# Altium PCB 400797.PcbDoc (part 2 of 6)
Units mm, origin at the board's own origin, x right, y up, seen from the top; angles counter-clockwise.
Board outline 155 x 63.5 mm, 4 copper layers (Top Layer, Mid-Layer 1, Mid-Layer 2, Bottom Layer), stack 1.514 mm thick; 317 components, 286 nets, 1519 pads, 2174 vias.
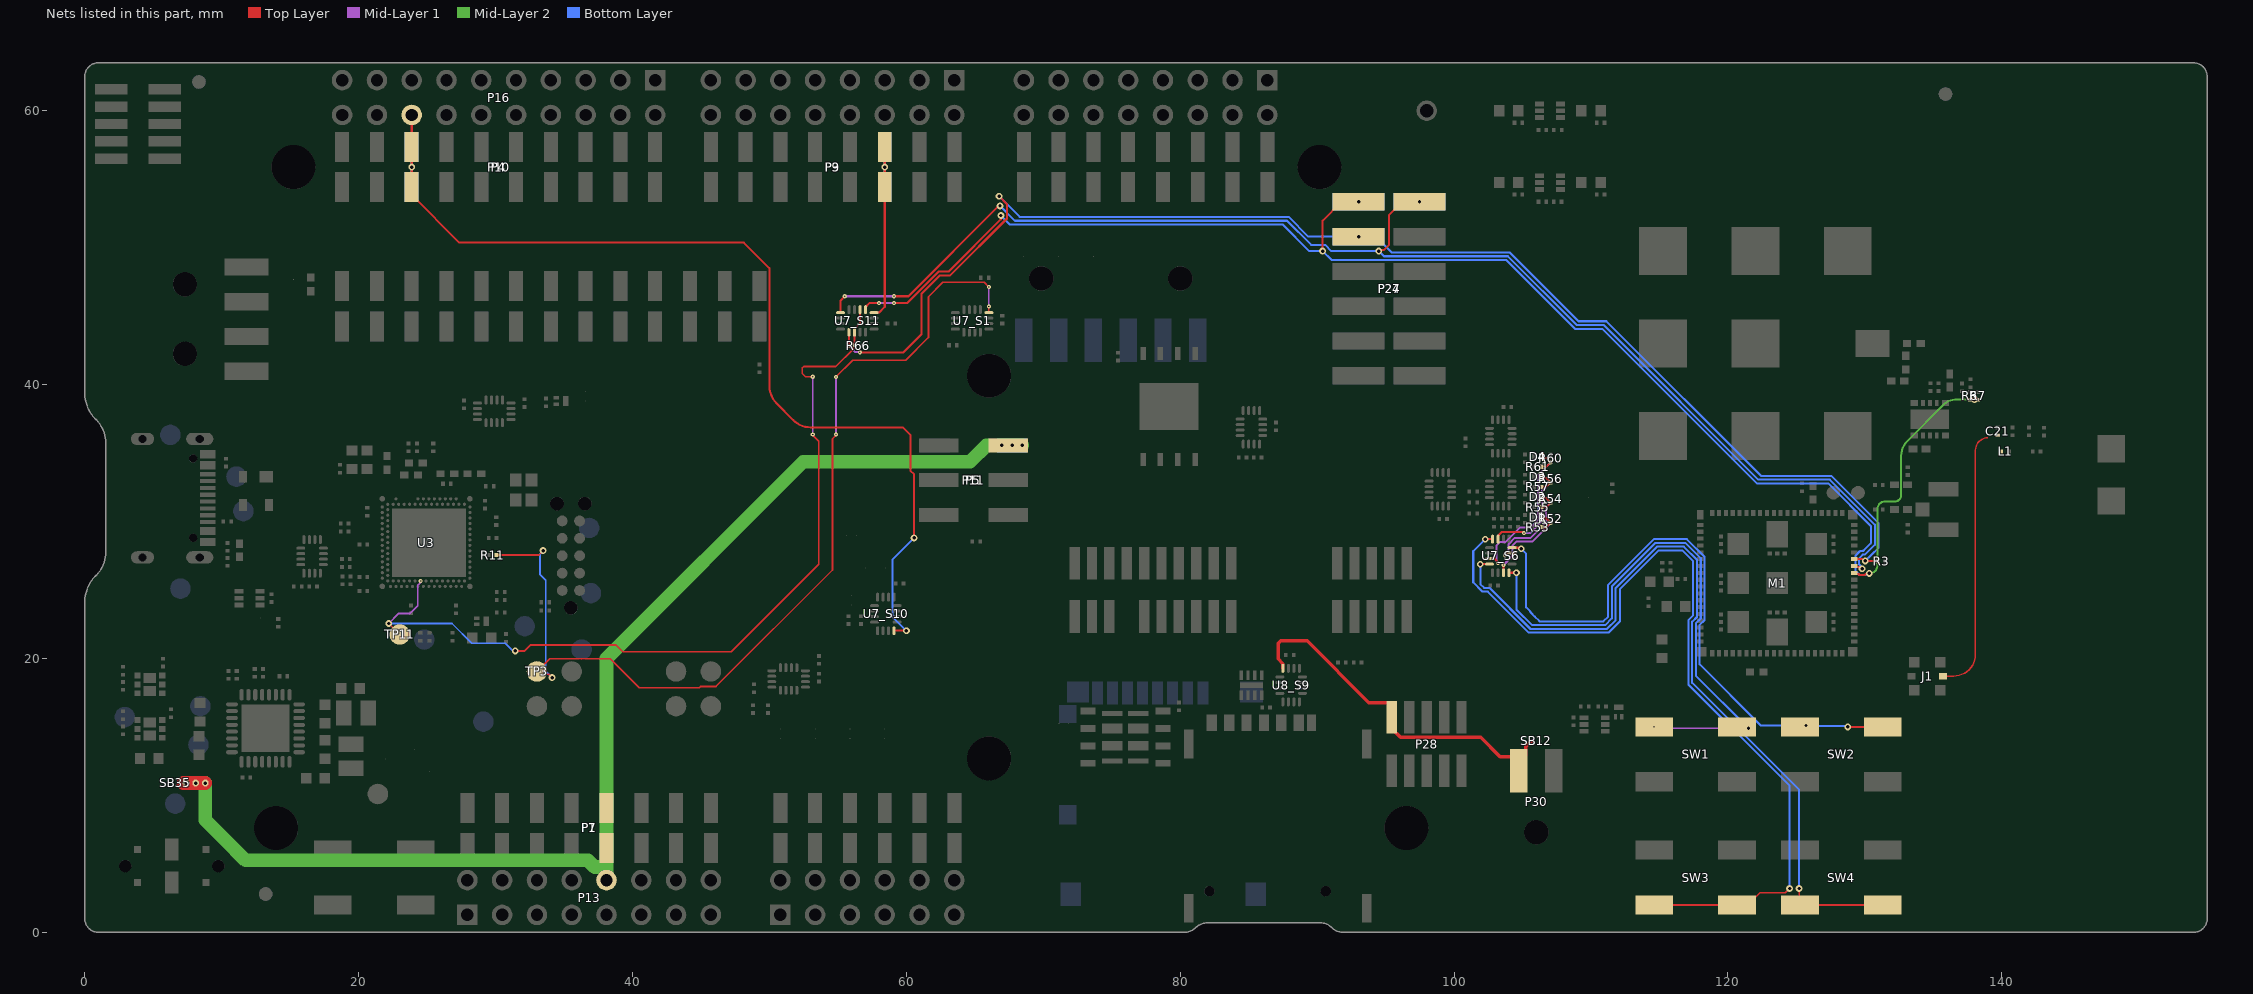
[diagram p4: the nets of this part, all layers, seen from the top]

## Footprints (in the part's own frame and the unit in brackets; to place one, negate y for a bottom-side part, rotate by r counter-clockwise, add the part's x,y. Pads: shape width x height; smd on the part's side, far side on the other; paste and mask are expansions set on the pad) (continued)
P822601 [mm] "Molded Diode, 2-Leads, Body 22,00x7,00mm, IPC Medium Density"
  rect 2x2 smd: 1(-8.89,-2.286) 2(-5.08,-2.286)
  Top Layer region: -21.6,1.254 -24.5,1.254 -24.5,3.754 -21.6,3.754
  Top Layer region: -22.4,-0.846 -24.5,-0.846 -24.5,0.854 -22.4,0.854
  Top Layer region: -21.6,-3.746 -24.5,-3.746 -24.5,-1.246 -21.6,-1.246
  Top Layer region: 24.6,-5.796 12.05,-5.796 12.05,-2.046 24.6,-2.046
  Top Layer region: 24.6,-2.046 21.7,-2.046 21.7,3.754 24.6,3.754
  Top Layer region: -3.67,-7.991 -8.05,-7.991 -8.05,-5.996 -3.67,-5.996
  Top Layer region: -3.67,-5.996 -5.71,-5.996 -5.71,-3.826 -3.67,-3.826
  Top Layer region: -3.67,-3.826 -6.399,-3.826 -6.4,-0.566 -3.67,-0.566
  Top Layer region: -10.45,-7.996 -12.45,-7.996 -12.45,-6.496 -10.45,-6.496
  Top Layer region: -9.2,-6.496 -12.45,-6.496 -12.45,-5.996 -9.2,-5.996
  Top Layer region: -9.45,-7.496 -9.95,-7.496 -9.95,-7.296 -9.45,-7.296
  Top Layer region: -8.45,-7.496 -8.95,-7.496 -8.95,-7.296 -8.45,-7.296
  Top Layer region: -8.45,-7.296 -9.95,-7.296 -9.95,-7.096 -8.45,-7.096
  Top Layer region: -9.45,-7.096 -9.95,-7.096 -9.95,-6.896 -9.45,-6.896
  Top Layer region: -8.45,-7.096 -8.95,-7.096 -8.95,-6.896 -8.45,-6.896
  Top Layer region: -8.6,-6.896 -8.8,-6.896 -8.8,-5.696 -8.6,-5.696
  Top Layer region: -8.2,-5.696 -9.2,-5.696 -9.2,-3.796 -8.2,-3.796
  Top Layer region: -7.3,-3.796 -10.4,-3.796 -10.4,-0.596 -7.3,-0.596
  Top Layer region: -9.45,-9.796 -9.95,-9.796 -9.95,-9.596 -9.45,-9.596
  Top Layer region: -8.45,-9.796 -8.95,-9.796 -8.95,-9.596 -8.45,-9.596
  Top Layer region: -8.45,-9.596 -9.95,-9.596 -9.95,-9.396 -8.45,-9.396
  Top Layer region: -9.45,-9.396 -9.95,-9.396 -9.95,-9.196 -9.45,-9.196
  Top Layer region: -8.45,-9.396 -8.95,-9.396 -8.95,-9.196 -8.45,-9.196
  Top Layer region: -9.6,-9.196 -9.8,-9.196 -9.8,-8.596 -9.6,-8.596
  Top Layer region: -9.45,-8.596 -9.95,-8.596 -9.95,-8.396 -9.45,-8.396
  Top Layer region: -8.45,-8.596 -8.95,-8.596 -8.95,-8.396 -8.45,-8.396
  Top Layer region: -8.45,-8.396 -9.95,-8.396 -9.95,-8.196 -8.45,-8.196
  Top Layer region: -9.45,-8.196 -9.95,-8.196 -9.95,-7.996 -9.45,-7.996
  Top Layer region: -8.45,-8.196 -8.95,-8.196 -8.95,-7.996 -8.45,-7.996
  Top Layer region: -9.6,-11.296 -9.8,-11.296 -9.8,-10.896 -9.6,-10.896
  Top Layer region: -9.45,-10.896 -9.95,-10.896 -9.95,-10.696 -9.45,-10.696
  Top Layer region: -8.45,-10.896 -8.95,-10.896 -8.95,-10.696 -8.45,-10.696
  Top Layer region: -8.45,-10.696 -9.95,-10.696 -9.95,-10.496 -8.45,-10.496
  Top Layer region: -9.45,-10.496 -9.95,-10.496 -9.95,-10.296 -9.45,-10.296
  Top Layer region: -8.45,-10.496 -8.95,-10.496 -8.95,-10.296 -8.45,-10.296
  Top Layer region: 24.75,-11.296 -8.05,-11.296 -8.05,-8.001 24.75,-8.001
  Top Layer region: -10.45,-11.296 -24.65,-11.296 -24.65,-7.996 -10.45,-7.996
  Bottom Layer region: -22.5,-3.546 -24.5,-3.546 -24.5,-2.546 -22.5,-2.546
  Bottom Layer region: -24.196,-2.546 -24.5,-2.546 -24.5,-2.046 -24.196,-2.046
  Bottom Layer region: -22.5,-2.046 -24.5,-2.046 -24.5,-1.046 -22.5,-1.046
  Bottom Layer region: -22.5,-1.046 -22.8,-1.046 -22.8,-0.546 -22.5,-0.546
  Bottom Layer region: -22.5,-0.546 -24.5,-0.546 -24.5,3.754 -22.5,3.754
  Bottom Layer region: -21,-3.546 -22,-3.546 -22,-1.046 -21,-1.046
  Bottom Layer region: -22.5,-5.046 -24.5,-5.046 -24.5,-4.046 -22.5,-4.046
  Bottom Layer region: 7.7,-5.796 6.7,-5.796 6.7,-4.896 7.7,-4.896
  Bottom Layer region: 9.2,-5.796 8.2,-5.796 8.2,-4.896 9.2,-4.896
  Bottom Layer region: 10.7,-5.796 9.7,-5.796 9.7,-4.896 10.7,-4.896
  Bottom Layer region: 13.2,-5.796 11.2,-5.796 11.2,-4.896 13.2,-4.896
  Bottom Layer region: 13.2,-4.896 6.7,-4.896 6.7,-4.596 13.2,-4.596
  Bottom Layer region: 7.7,-4.596 6.7,-4.596 6.7,-3.746 7.7,-3.746
  Bottom Layer region: 9.2,-4.596 8.2,-4.596 8.2,-3.746 9.2,-3.746
  Bottom Layer region: 10.7,-4.596 9.7,-4.596 9.7,-3.746 10.7,-3.746
  Bottom Layer region: 13.2,-4.596 11.2,-4.596 11.2,-3.746 13.2,-3.746
  Bottom Layer region: 6.2,-5.796 5.2,-5.796 5.2,-3.746 6.2,-3.746
  Bottom Layer region: 4.7,-5.796 3.7,-5.796 3.7,-3.746 4.7,-3.746
  Bottom Layer region: -3.86,-7.996 -12.45,-7.996 -12.45,-5.996 -3.86,-5.996
  Bottom Layer region: 24.752,-11.296 -24.648,-11.296 -24.65,-7.996 24.75,-7.996
  Multi-Layer pour cut-out: -39.95,5.08 39.05,5.08 39.05,-7.996 -39.95,-7.996
  silkscreen extent -25.2,-4.25 25.3,4.05, body extent -24.95,-4 25.05,4, height 3.2
RESC0603X03L_C [mm] "Chip Resistor, 2-Leads, Body 0.6x0.3mm, IPC High Density"
  rect 0.27x0.3 smd: 1(-0.285,0) 2(0.285,0)
  body extent -0.3,-0.15 0.3,0.15, height 0.23
RESC0603X03L_C_NC [mm] "Chip Resistor, 2-Leads, Body 0.6x0.3mm, IPC High Density"
  rect 0.27x0.3 smd: 1(-0.285,0) 2(0.285,0)
RESC1005X04L [mm] "Chip Resistor, 2-Leads, Body 1.0x0.5mm, IPC High Density"
  rect 0.6x0.55 smd mask+0.05: 1(-0.5,0) 2(0.5,0)
  body extent -0.5,-0.25 0.5,0.25, height 0.3
RESC1005X04L_NC [mm] "Chip Resistor, 2-Leads, Body 1.0x0.5mm, IPC High Density"
  rect 0.6x0.55 smd mask+0.05: 1(-0.5,0) 2(0.5,0)
SD-80259-001 [mm] "USB TYPE C RECEPTACLE, 16 PIN"
  round 0.6 hole 0.6 unplated: 0(-2.89,1.315) 0(2.89,1.315)
  oval 0.9x2 hole 0.6 slot 1.7 at 90 deg: 13(-4.325,1.795) 13(4.325,1.795)
  oval 0.9x1.7 hole 0.6 slot 1.4 at 90 deg: 13(-4.325,-2.385) 13(4.325,-2.385)
  rect 0.6x1.14 smd: A1(-3.2,2.385) A4(-2.4,2.385) A9(2.4,2.385) A12(3.2,2.385)
  rect 0.3x1.14 smd: A5(-1.25,2.385) A6(-0.25,2.385) A7(0.25,2.385) A8(1.25,2.385) B5(1.75,2.385) B6(0.75,2.385) B7(-0.75,2.385) B8(-1.75,2.385)
  oval 0.9x2 on Top Paste: ""(-4.32,1.795) ""(4.32,1.795)
  oval 0.9x1.7 on Top Paste: ""(-4.32,-2.385) ""(4.32,-2.385)
  silkscreen extent -4.33,-4.48 4.33,0.47, body extent -4.48,-4.98 4.48,2.74, height 3.26
SEGGER_LOGO_S [mm] "Logo 7.82 mm x 3.84 mm, print overlay"
  silkscreen extent -3.91,-1.92 3.91,1.92
Shunt_2.54mm_Horizontal [mm]
  body extent 0,-2.54 5.03,2.54, height 2.99
SKY65943-11 [mm]
  rect 0.425x0.515 smd mask+0.05: 1(-1.188,1.144) 5(-1.188,-1.144) 6(1.188,-1.144) 10(1.188,1.144)
  rect 0.425x0.275 smd mask+0.05: 2(-1.188,0.5) 3(-1.188,0) 4(-1.188,-0.5) 7(1.188,-0.5) 8(1.188,0) 9(1.188,0.5)
  rect 1.45x2.802 smd paste-2 mask-5: 11(0,0)
  rect 1.55x2.487 on Top Solder: ""(0,0)
  Top Layer region: -0.988,0.887 -0.713,0.887 -0.713,1.4 -0.988,1.4
  Top Layer region: 0.713,-1.4 0.988,-1.4 0.988,-0.887 0.713,-0.887
  Top Layer region: 0.712,0.362 0.987,0.362 0.987,0.637 0.712,0.637
  Top Layer region: -0.712,-0.362 -0.987,-0.362 -0.987,-0.637 -0.712,-0.637
  body extent -1.25,-1.25 1.25,1.25, height 0.71
SOCKET_1x6_SMD [mm] "Socket, 2.54mm, SMD"
  rect 1.02x2.19 smd: 1(0,-1.465) 1(0,1.465) 2(2.54,-1.465) 2(2.54,1.465) 3(5.08,-1.465) 3(5.08,1.465) 4(7.62,-1.465) 4(7.62,1.465) 5(10.16,-1.465) 5(10.16,1.465) 6(12.7,1.465) 6(12.7,-1.465)
  silkscreen extent -1.27,-1.27 13.97,1.27, body extent -1.27,-2.29 13.97,2.29, height 7.47
SOCKET_1x8_SMD [mm] "Socket, 2.54mm, SMD"
  rect 1.02x2.19 smd: 1(0,-1.465) 1(0,1.465) 2(2.54,-1.465) 2(2.54,1.465) 3(5.08,-1.465) 3(5.08,1.465) 4(7.62,-1.465) 4(7.62,1.465) 5(10.16,-1.465) 5(10.16,1.465) 6(12.7,1.465) 6(12.7,-1.465) 7(15.24,-1.465) 7(15.24,1.465) 8(17.78,-1.465) 8(17.78,1.465)
  silkscreen extent -1.27,-1.27 19.05,1.27, body extent -1.27,-2.29 19.05,2.29, height 7.47
SOCKET_1x10_SMD [mm] "Socket, 2.54mm, SMD"
  rect 1.02x2.19 smd: 1(0,1.465) 1(0,-1.465) 2(2.54,-1.465) 2(2.54,1.465) 3(5.08,-1.465) 3(5.08,1.465) 4(7.62,-1.465) 4(7.62,1.465) 5(10.16,-1.465) 5(10.16,1.465) 6(12.7,-1.465) 6(12.7,1.465) 7(15.24,-1.465) 7(15.24,1.465) 8(17.78,-1.465) 8(17.78,1.465) 9(20.32,-1.465) 9(20.32,1.465) 10(22.86,-1.465) 10(22.86,1.465)
  silkscreen extent -1.27,-1.27 24.13,1.27, body extent -1.27,-2.29 24.13,2.29, height 7.47
SOCKET_2x3_SMD-2.54mm-bottom-NC [mm] "Socket, 2.54mm, SMD"
  rect 1.02x2.22 smd far side: 1(-2.54,-2.825) 2(-2.54,2.825) 3(0,-2.825) 4(0,2.825) 5(2.54,-2.825) 6(2.54,2.825)
SOCKET_2x6_SMD-2.54mm#1 [mil]
  rect 50x150 smd: 1(-250,-87.5) 2(-250,87.5) 3(-150,-87.5) 4(-150,87.5) 5(-50,-87.5) 6(-50,87.5) 7(50,-87.5) 8(50,87.5) 9(150,-87.5) 10(150,87.5) 11(250,-87.5) 12(250,87.5)
  silkscreen extent -310,-127 300,100, body extent -300,-138 300,139, height 290
SOCKET_2x6_SMD-2.54mm#2 [mil] "Board-Board Conn, Header, 4-way, 2-row"
  rect 50x150 smd: 1(-250,87.5) 2(-250,-87.5) 3(-150,87.5) 4(-150,-87.5) 5(-50,87.5) 6(-50,-87.5) 7(50,87.5) 8(50,-87.5) 9(150,87.5) 10(150,-87.5) 11(250,87.5) 12(250,-87.5)
  silkscreen extent -310,-100 300,127
SODFL35X40-2N [mm] "SODFL, 2-Leads, Body 0,60x0,35mm, IPC Medium Density"
  rect 0.25x0.6 smd: 1(-0.325,0) 3(0.325,0)
  body extent -0.53,-0.33 0.53,0.33, height 0.4
Solderbridge [mil]
  round 1 smd paste-99999: 1(-13.78,0) 2(13.78,0)
  Top Layer region: -7.49,19.36 -15.76,15.74 -21.55,8.8 -23.62,0 -23.62,0 -21.55,-8.79 -15.76,-15.74 -7.49,-19.36 -7.49,-19.36 -6.18,-19.31 -5.02,-18.71 -4.22,-17.68 -3.94,-16.4 -3.94,-16.4 -3.94,16.4 -4.22,17.68 -5.02,18.71 -6.18,19.31 -7.49,19.36
  Top Layer region: 7.49,-19.36 15.76,-15.74 21.55,-8.8 23.62,0 23.62,0 21.55,8.79 15.76,15.74 7.49,19.36 7.49,19.36 6.18,19.31 5.02,18.71 4.22,17.68 3.94,16.4 3.94,16.4 3.94,-16.4 4.22,-17.68 5.02,-18.71 6.18,-19.31 7.49,-19.36
Solderbridge_Shorted [mil]
  round 1 smd paste-99999: 1(-13.78,0) 2(13.78,0)
  Top Layer region: -4.92,3.94 -4.92,-3.94 4.92,-3.94 4.92,3.94
  Top Layer region: -7.49,19.36 -15.76,15.74 -21.55,8.8 -23.62,0 -23.62,0 -21.55,-8.79 -15.76,-15.74 -7.49,-19.36 -7.49,-19.36 -6.18,-19.31 -5.02,-18.71 -4.22,-17.68 -3.94,-16.4 -3.94,-16.4 -3.94,16.4 -4.22,17.68 -5.02,18.71 -6.18,19.31 -7.49,19.36
  Top Layer region: 7.49,-19.36 15.76,-15.74 21.55,-8.8 23.62,0 23.62,0 21.55,8.79 15.76,15.74 7.49,19.36 7.49,19.36 6.18,19.31 5.02,18.71 4.22,17.68 3.94,16.4 3.94,16.4 3.94,-16.4 4.22,-17.68 5.02,-18.71 6.18,-19.31 7.49,-19.36
Solderbridge_Shorted_Power [mil]
  round 1 smd paste-99999: 1(-13.84,0.21) 2(13.72,0.21)
  Top Layer region: -4.92,9.84 4.92,9.84 4.92,-9.84 -4.92,-9.84
  Top Layer region: 7.43,-19.16 15.71,-15.53 21.49,-8.59 23.56,0.21 23.56,0.21 21.49,9 15.71,15.94 7.43,19.57 7.43,19.57 6.12,19.52 4.96,18.92 4.16,17.89 3.88,16.61 3.88,16.61 3.88,-16.2 4.16,-17.47 4.96,-18.51 6.12,-19.11 7.43,-19.16
  Top Layer region: -7.54,19.57 -15.82,15.94 -21.61,9 -23.68,0.21 -23.68,0.21 -21.61,-8.59 -15.82,-15.53 -7.54,-19.16 -7.54,-19.16 -6.24,-19.11 -5.08,-18.51 -4.28,-17.47 -4,-16.2 -3.99,-16.2 -3.99,16.61 -4.28,17.89 -5.08,18.92 -6.24,19.52 -7.54,19.57
SON50P210X160X65_HS-9N [mm] "SON, 8-Leads, Body 2.10x1.60mm, Pitch 0.50mm, Thermal Pad 1.70x0.4mm, IPC Medium Density"
  rect 0.7x0.25 smd mask+0.05: 1(-0.725,0.75) 2(-0.725,0.25) 3(-0.725,-0.25) 4(-0.725,-0.75) 5(0.725,-0.75) 6(0.725,-0.25) 7(0.725,0.25) 8(0.725,0.75)
  rect 0.4x1.7 smd paste-2 mask+0.05: 9(0,0)
  rect 0.3x0.75 on Top Paste: ""(0,0.425) ""(0,-0.425)
  silkscreen extent -1.26,1.2 -1.16,1.26, body extent -0.85,-1.1 0.85,1.1, height 0.65
SON127P600X90_HS-8N [mm] "SON, 8-Leads, Body 5.00x6.00mm, Pitch 1.27mm, IPC Medium Density"
  rect 1.5x0.35 smd paste-1.27: 0(-0.95,-1.73) 0(-0.95,1.73) 0(0.95,-1.73) 0(0.95,1.73)
  rect 1.5x0.7 smd paste-1.27: 0(-0.95,-0.635) 0(-0.95,0.635) 0(0.95,-0.635) 0(0.95,0.635)
  rect 1.1x0.5 smd paste-1.27: 1(-2.75,1.905) 2(-2.75,0.635) 3(-2.75,-0.635) 4(-2.75,-1.905) 5(2.75,-1.905) 6(2.75,-0.635) 7(2.75,0.635) 8(2.75,1.905)
  silkscreen extent -3.6,-2.58 3.08,2.72, body extent -3,-2.5 3,2.5, height 0.65
SON127P800X80_HS-9N [mm] "SON, 8-Leads, Body 6.00x8.00mm, Pitch 1.27mm, Thermal Pad 4.30x3.40mm, IPC Medium Density"
  rect 0.95x0.4 smd: 1(-3.87,1.905) 2(-3.87,0.635) 3(-3.87,-0.635) 4(-3.87,-1.905) 5(3.87,-1.905) 6(3.87,-0.635) 7(3.87,0.635) 8(3.87,1.905)
  rect 3.4x4.3 smd paste-1.7: 9(0,0)
  silkscreen extent -4.52,-3.18 4.18,3.52, body extent -4.05,-3.05 4.05,3.05, height 0.8
SOT190P230X110-4L [mm] "SOT143, 4-Leads, Body 3.0x2.5mm (max), Pitch 1.90mm, IPC High Density"
  rect 0.85x1 smd: 1(-1.025,0.75)
  rect 0.85x0.6 smd: 2(-1.025,-0.95) 3(1.025,-0.95) 4(1.025,0.95)
  silkscreen extent -1.15,-1.5 0.25,1.93, body extent -1.21,-1.46 1.21,1.46, height 1
SOTFL50P162X60-6N [mm] "SOTFL, 6-Leads, Body 1.60x1.63mm, Pitch 0.50mm, IPC Medium Density"
  rect 0.65x0.35 smd: 1(-0.775,0.5) 2(-0.775,0) 3(-0.775,-0.5) 4(0.775,-0.5) 5(0.775,0) 6(0.775,0.5)
  silkscreen extent -0.9,-0.82 0.05,1.35, body extent -0.81,-0.85 0.81,0.85, height 0.6
TC2050-IDC-NLFP [mil]
  round 39 hole 39 unplated: 0(-150,0) 0(150,-40) 0(150,40)
  round 31 smd paste-196.85: 1(-100,-25) 2(-50,-25) 3(0,-25) 4(50,-25) 5(100,-25) 6(100,25) 7(50,25) 8(0,25) 9(-50,25) 10(-100,25)
  Top Layer pour cut-out: -100,25 -100,-25 100,-25 100,25
TESTPAD-TH [mm]
  round 1.5 hole 1: 1(0,0)
TP_SMD_D1.0mm [mm] "Test point - pad 1.0mm"
  round 1 smd paste-5: 1(0,0)
TP_SMD_D1.5mm [mm] "Test point - pad 1.5mm"
  round 1.5 smd paste-5: 1(0,0)
  body extent -0.75,-0.75 0.75,0.75, height 0.05
WEE_3x4.5mm [mm]
  silkscreen extent -1.47,-2.7 1.47,1.71
XQFN40P180X260X50-16N [mm] "QFN, 16-Leads, Body 1.80x2.60mm, Pitch 0.40mm, IPC Medium Density"
  oval 0.65x0.22 smd paste-0.02 mask+0.04: 1(-0.825,0.6) 2(-0.825,0.2) 3(-0.825,-0.2) 4(-0.825,-0.6) 9(0.825,-0.6) 10(0.825,-0.2) 11(0.825,0.2) 12(0.825,0.6)
  oval 0.22x0.65 smd paste-0.02 mask+0.04: 5(-0.6,-1.225) 6(-0.2,-1.225) 7(0.2,-1.225) 8(0.6,-1.225) 13(0.6,1.225) 14(0.2,1.225) 15(-0.2,1.225) 16(-0.6,1.225)
  body extent -0.91,-1.31 0.91,1.31, height 0.55

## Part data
A1: "ANTENNA PRESTTA OCTABAND LTE", Manufacturer=Ethertronics, Part number IPS=00000009001, Part number NEMS=100700043, Part number Norautron=N.A.
A2: library part DSGP.1575.18.4.C.02, "18 x 18 mm Low Profile GPS L1 / GALILEO E1 Passive Patch Antenna", Manufacturer=Taoglas, Part number IPS=00000007687, Part number NEMS=100700073, Part number Norautron=N.A.
C1 C2: library part C0201-1Âµ0-10V-X5R-GRM033R61A105ME15, "Capacitor, X5R, Â±20%, 10V", Manufacturer=Murata, Manufacturer Part Number=GRM033R61A105ME15, Part number IPS=N.A., Part number NEMS=100200545, Supplier Part Number 1=490-13226-1-ND
C3 C7: library part C0603-10Âµ-10V-X6S-GRM188C81A106MA73, "Capacitor, Ceramic, 10ÂµF 10V X6S 0603,Â±20%", Manufacturer=Murata, Manufacturer Part Number=GRM188C81A106MA73, Part number IPS=N.A., Part number NEMS=100200520, Supplier Part Number 1=490-7197-2-ND
C4 C10 C15 C16 C24 C25 C26 C27 C31 C32 C33 C34 C39 C42 C43 C51 C52_S1 C52_S2 C52_S3 C52_S4 C52_S5 C52_S6 C52_S8 C52_S10 C52_S11 C53_S7 C53_S9 C62: library part C0201-100n, "Capacitor, X5R, Â±10%", Manufacturer=N.A., Part number IPS="00000001248, 00000002505", Part number NEMS=100200078, Part number Norautron=262071862
C5 C6: library part C0402-4Âµ7-10V-X5R, "Capacitor, X5R, 10V", Manufacturer=Murata, Manufacturer Part Number=GRM155R61A475MEAAD, Part number IPS=N.A., Part number NEMS=100200415, Supplier Part Number 1=490-14306-1-ND
C11 C12 C13: library part C0201-39p, "Capacitor, NP0, Â±1%, 25V", Manufacturer=Murata, Manufacturer Part Number=GRM0335C1E390FA01, Part number IPS=00000001668, Part number NEMS=100200039, Part number Norautron=N.A.
C14 C17: library part C0201-100p, "Capacitor, NP0, Â±2%, 25V", Manufacturer=Murata, Manufacturer Part Number=GRM0335C1E101GA01, Part number IPS=00000007853, Part number NEMS=100200044, Part number Norautron=N.A.
C18: library part C0402-N.C., "Not mounted", Manufacturer=N.A., Part number NEMS=100200105
C19 C21 C22 C23 C49: library part C0201-N.C., "Not mounted", Manufacturer=N.A., Part number NEMS=100200001
C20: library part C0201-3.5p, "Capacitor, NP0, Â±0.1pF, 25V", Manufacturer=Murata, Manufacturer Part Number=GJM0335C1H3R5BB01E, Part number IPS=00000001469, Part number NEMS=100200023, Part number Norautron=N.A.
C28 C29 C35 C36 C40: library part C0402-1Âµ0-10V-X5R, "Capacitor, Ceramic, X5R, Â±10%, 10V", Manufacturer=N.A., Part number NEMS=100200482
C30: library part C0201-2n2, "Capacitor, X7R, Â±10%, 10V", Manufacturer=N.A., Part number IPS=00000001778, Part number NEMS=100200060, Part number Norautron=26470002
C37 C38 C58: library part C0603-4Âµ7-10V-X5R, "Capacitor, Ceramic, X5R, Â±10%, 10V", Manufacturer=N.A., Part number NEMS=100200479, Part number Norautron=262081761
C41 C48 C50: library part C0201-10n, "Capacitor, X7R, Â±10%", Manufacturer=N.A., Part number IPS=00000003480, Part number NEMS=100200067, Part number Norautron=26621779
C44 C45 C46 C47: library part C0201-1Âµ0, "Capacitor, X5R, Â±10%", Manufacturer=N.A., Part number IPS=00000001723, Part number NEMS=100200084, Supplier Part Number 1=1276-6795-1-ND
C54: library part C0603-1Âµ0-10V-X5R, "Capacitor, Ceramic, 1.0ÂµF 10V X5R 0603,Â±10%", Manufacturer=N.A., Part number NEMS=100200528
C55 C56 C57 C59 C60: library part C0603-10Âµ-10V-X7T-GRM188D71A106MA73, "Capacitor, X7T, Â±20%, 10V", Manufacturer=Murata, Manufacturer Part Number=GRM188D71A106MA73, Part number IPS=00000004696, Part number NEMS=100200414, Part number Norautron=N.A., Supplier Part Number 1=490-7200-1-ND
D1 D2 D3 D4: "DIODE SCHOTTKY 20V 500MA SOD882", Manufacturer="Central Semiconductor Corp.", Part number IPS=00000002493, Part number NEMS=101300101, Part number Norautron=N.A., Supplier Part Number 1="CFSH05-20L CT-ND"
D5: "ESD Protection and EMI Filter for SIM Card Interface", Manufacturer="Texas Instruments", Part number IPS=N.A., Part number NEMS=101900729, Supplier Part Number 1=296-28299-1-ND
D6: "Ultra low capacitance double rail-to-rail ESD protection diode", Manufacturer="NXP Semiconductors", Part number IPS=00000009951, Part number NEMS=101300082, Part number Norautron=26313940, Supplier Part Number 1=568-4140-1-ND
FB1: library part FB0603-22R@100MHz-6000mA, "Ferrite Bead, 22 Ohm @ 100MHz, 6000mA, 8 mOhm Max", Manufacturer=Murata, Manufacturer Part Number=BLM18SD220SN1D, Part number IPS=N.A., Supplier Part Number 1=490-15633-2-ND
FB2: library part FB0402-120R@100M-500mA, "Ferrite Bead, 120 Ohm @ 100MHz, 500mA, 250 mOhm Max", Manufacturer=Murata, Manufacturer Part Number=BLM15AG121SN1D, Part number IPS=00000009954, Part number NEMS=100300099, Part number Norautron=265230631, Supplier Part Number 1=490-1005-1-ND
FB3: library part FB0402-120R@100M-1200mA, "Ferrite Bead, 120 Ohm @ 100MHz, 1200mA, 75 mOhm Max", Manufacturer=Murata, Manufacturer Part Number=BLM15EX121SN1, Part number IPS=N.A., Part number NEMS=100300416, Supplier Part Number 1=490-16509-1-ND
Fid1 Fid2 Fid3: library part Fid-Mark, "Fiducial Mark", Manufacturer=N.A., Part number NEMS=100500073
J1: "Coaxial Connector with Switch", Manufacturer=Murata, Part number IPS=00000009955, Part number NEMS=100500400, Part number Norautron=26030338, Supplier Part Number 1=490-4981-1-ND
J2: library part 20279-001E-03, "Ultraminiature Coaxial Connector, 50 Ohm, SMD", Manufacturer=Wellshow, Part number IPS=00000004436, Part number NEMS=100500636, Part number Norautron=N.A.
J4: library part TC2050-IDC-NLFP, "CBL PLUG-OF-NAILS 10-PIN", Manufacturer="Tag-Connect LLC", Part number IPS=N.A., Part number NEMS=100500463, Supplier Part Number 1=TC2050-IDC-NL-ND
J5: library part L-KLS1-SIM-066-(6+1)P-H1.37-R, "Nano SIM Card Connector, Push-Push, 6-Pin, H1.37mm, with CD Pin", Manufacturer="KLS Electronic", Part number IPS=N.A., Part number NEMS=100500776
J6: library part 80259-1021, "USB-C Receptacle, 16 Pin, USB 2.0", Manufacturer="Bellweather Electronic Corp.", Part number IPS=N.A., Part number NEMS=100500830
J8: library part Molex_502774-0891, "1.10mm Pitch microSD Memory Card Connector, Reverse Mount Surface Mount, Push-Push Type", Manufacturer=Molex, Manufacturer Part Number=502774-0891, Part number IPS=00000001284, Part number NEMS=100500509, Part number Norautron=N.A., Supplier Part Number 1=WM24066CT-ND
L1: library part L0201-1n5-HQ-Murata, "Inductor, 1000mA, Â±0.1ï½ŽH, 50mOhm", Manufacturer=Murata, Manufacturer Part Number=LQP03HQ1N5B02, Part number IPS=N.A., Part number NEMS=100300202, Supplier Part Number 1=490-13881-1-ND
L2: library part L0201-22n, "Chip Inductor", Manufacturer=N.A., Part number IPS=00000001478, Part number NEMS=100300034
L3: library part L0402-68n-Wirewound-Murata, "Inductor, 140mA, Â±2%, 1960mÎ©, Q=20", Manufacturer=Murata, Manufacturer Part Number=LQW15AN68NG00, Part number IPS=00000002494, Part number NEMS=100300389, Part number Norautron=N.A., Supplier Part Number 1=490-6837-1-ND
L4 L5: library part L0402-N.C., "Not mounted", Manufacturer=N.A., Part number NEMS=100300037
L6: library part L0402-9n1-Wirewound-Murata, "Inductor, 540mA, Â±2%, 140mÎ©, Q=25", Manufacturer=Murata, Manufacturer Part Number=LQW15AN9N1G00, Part number IPS=00000002497, Part number NEMS=100300357, Part number Norautron=N.A., Supplier Part Number 1=490-6854-1-ND
L7 L8: library part L0806-2Âµ2-2500mA-73mOhm-CIGT201610EH2R2MNE, "Inductor, Irms=2.5A, Isat=2.9A, Â±20%, DCR=73mÎ©", Manufacturer="Samsung Electro-Mechanics America", Manufacturer Part Number=CIGT201610EH2R2MNE, Part number IPS=N.A., Part number NEMS=100300400, Part number Norautron=26521789, Supplier Part Number 1=1276-6901-1-ND
LABEL1: library part Label_15x40, "PCA version label, stick-on, 15x40mm", Manufacturer="Ellco Etikett", Manufacturer Part Number=51945, Part number IPS=N.A., Part number NEMS=101200030
LED1 LED2 LED3 LED4 LED5: library part "VS 25C7M5", "LED, Green, 0603, 573nm, Vf=2.0V, 24mcd, - 40 to +85Â°C", Manufacturer="Victory Electronics", Part number IPS="00000001274, 00000009961", Part number NEMS=101400097, Part number Norautron=26313411, Supplier Part Number 1=N.A.
LOGO1: library part "WEEE Symbol 3x4.5mm", "WEEE Directive symbol", Manufacturer=N.A., Part number NEMS=101100006
LOGO2: "Segger logo, small size", Manufacturer=N.A., Part number NEMS=101100004
LOGO3: library part "Nordic Logo lying", "Nordic logo lying", Manufacturer=N.A., Part number NEMS=101100001
M1: "Low power System-in-Package with integrated LTE-M/NB-IoT modem and GPS", Manufacturer="Nordic Semiconductor", Part number IPS=N.A.
P1 P3 P6: library part "Socket 1x8 SMD", "Socket 1x8, 2.54mm (100mil), SMD", Manufacturer=WCON, Manufacturer Part Number=2171-108MS0CUNR1, Part number IPS=00000009963, Part number NEMS=100500412, Part number Norautron=26032369
P2: library part "Socket 1x6 SMD", "Socket 1x6, 2.54mm (100mil), SMD", Manufacturer=WCON, Manufacturer Part Number=2171-106MS0CUNR1, Part number IPS=00000009964, Part number NEMS=100500408, Part number Norautron=26032370
P4: library part "Socket 1x10 SMD", "Socket 1x10, 2.54mm (100mil), SMD", Manufacturer=WCON, Manufacturer Part Number=2171-110MS0CUNR1, Part number IPS=00000009965, Part number NEMS=100500416, Part number Norautron=26032371
P5: library part "Pin Header 2x3 SMD", "Pin Header 2x3, 2.54mm (100mil) SMD", Manufacturer=WCON, Manufacturer Part Number=1125-1203S0M116R1, Part number IPS=00000009966, Part number NEMS=100500242, Part number Norautron=N.A.
P7 P9 P12: library part "Pin List 1x8 SMD, N.C.", "Pin List 1x8, 2.54mm (100mil), SMD", Manufacturer=WCON, Manufacturer Part Number=1125-1108S0M116R2, Part number IPS=N.A., Part number NEMS=100500330
P8: library part "Pin List 1x6 SMD, N.C.", "Pin List 1x6, 2.54mm (100mil), SMD", Manufacturer=WCON, Manufacturer Part Number=1125-1106S0M116R2, Part number IPS=N.A., Part number NEMS=100500321
P10: library part "Pin List 1x10 SMD, N.C.", "Pin List 1x10, 2.54mm (100mil), SMD", Manufacturer=WCON, Manufacturer Part Number=1125-1110S0M116R2, Part number IPS=N.A., Part number NEMS=100500338
P11: library part "Socket 2x3 SMD Bottom, N.C.", "Socket 2x3, 2.54mm (100mil), SMD", Manufacturer=WCON, Manufacturer Part Number=2171-203MS0CUNR1, Part number IPS=N.A., Part number NEMS=100500434
P13 P15 P17: library part "Pin Header 2x8, N.C.", "Pin Header 2x8, 2.54mm (100mil)", Manufacturer=N.A., Part number NEMS=100500270
P14: library part "Pin Header 2x6, N.C.", "Pin Header 2x6, 2.54mm (100mil)", Manufacturer=N.A., Part number NEMS=100500265
P16: library part "Pin Header 2x10, N.C.", "Pin Header 2x10, 2.54mm (100mil)", Manufacturer=N.A., Part number NEMS=100500274
P18 P19: library part "Pin Header 2x5 SMD, 1.27mm, KS", "Pin Header 2x5, 1.27mm (50mil), SMD, Keying Shroud", Manufacturer=WCON, Manufacturer Part Number=3132-10MS0BK00R1, Part number IPS=00000009968, Part number NEMS=100500261, Part number Norautron=N.A.
P20: library part "Pin List 1x13 SMD", "Pin List 1x13, 2.54mm (100mil), SMD", Manufacturer=N.A., Part number IPS=00000002499, Part number NEMS=100500345, Supplier Part Number 1=1125-1113S0M116R2
P22: library part "Pin List Ang 1x4 SMD, 2.54mm", "Pin List 1x4, 2.54mm (100mil), Right Angled, SMD", Manufacturer=WCON, Manufacturer Part Number=1125B-1104S0Z135CR02, Part number IPS=00000004780, Part number NEMS=100500358, Part number Norautron=N.A.
P24 P27: library part "Socket 2x6 SMD", "Socket 2x6, 2.54mm (100mil), SMD", Manufacturer=WCON, Manufacturer Part Number=2171-206MS0CUNR1, Part number IPS=N.A., Part number NEMS=100500439
P25: library part "Pin Header 2x10 SMD, 1.27mm, KS, SWD (Cabcon)", "Pin Header 2x10, 1.27mm (50mil), SMD, Keying Shroud, Removed Pin 7", Manufacturer=WCON, Manufacturer Part Number=3132-20MS0BK00R3, Part number IPS=N.A., Part number NEMS=100500841,100500280
P26: library part "Socket 1x13 SMD, N.C.", "Socket 1x13, 2.54mm (100mil), SMD", Manufacturer=WCON, Manufacturer Part Number=2171-113MS0CUNR1, Part number IPS=N.A., Part number NEMS=100500422
P28: library part "Pin Header 2x5 SMD, 1.27mm", "Pin Header 2x5, 1.27mm (50mil), SMD", Manufacturer=WCON, Manufacturer Part Number=1325-1205S0M078R1, Part number IPS=00000009970, Part number NEMS=100500259, Part number Norautron=N.A.
P29: library part "Pin List Ang 1x6 SMD, 2.54mm", "Pin List 1x6, 2.54mm (100mil), Right Angled, SMD", Manufacturer=N.A., Part number IPS=00000003922, Part number NEMS=100500362, Supplier Part Number 1=TSM-106-01-L-SH-A
P30: library part "Pin List Ang 1x2 SMD, 2.54mm", "Pin List 1x2, 2.54mm (100mil), Right Angled, SMD", Manufacturer=WCON, Manufacturer Part Number=1125B-1102S0Z135R2, Part number IPS=00000009972, Part number NEMS=100500354, Part number Norautron=N.A.
Q1 Q7: "Dual N & P Ch MOFET, 1.03A/0.7A, 480mOhm, 450mW", Manufacturer="Diodes Incorporated", Part number IPS=00000007803, Part number NEMS=101300117, Part number Norautron=N.A., Supplier Part Number 1=DMC2400UV-7DICT-ND
Q2 Q3 Q6: "N-Channel MOSFET, 20V, 1A, 470mOhm, 400mW", Manufacturer="Rohm Semiconductor", Part number IPS=00000009976, Part number NEMS=101300132, Part number Norautron=26320026, Supplier Part Number 1=RV2C010UNT2LCT-ND
Q4 Q5: "Dual N-Channel MOSFET, Vds = 30V, Vgs(th) = 1.5V, Id = 0.5A, Rds = 750mOhm, Pd = 150mW", Manufacturer="Micro Commercial Components", Manufacturer Part Number=UM6X1NA-TP, Part number IPS=N.A., Part number NEMS=101300201, Supplier Part Number 1=353-UM6X1NA-TPCT-ND
Q8 Q9: "Dual P-Channel MOFET, 3.8A, 90mOhm max, 1.4W", Manufacturer="Micro Commercial Components", Part number IPS=N.A., Part number NEMS=101300199, Supplier Part Number 1=MCM2301-TPMSCT-ND
R1 R8 R77 R79: library part R0201-10k, "Resistor, Â±1%, 0.05W", Manufacturer=N.A., Part number IPS=00000001255, Part number NEMS=100100065, Part number Norautron=26107101
R2 R6: library part R0201-1k0, "Resistor, Â±1%, 0.05W", Manufacturer=N.A., Part number IPS=00000005786, Part number NEMS=100100043
R3 R7 R13 R14 R17 R18 R24 R31 R32 R38 R43 R44 R45 R46 R47 R62 R66 R67 R69 R72 R73 R75 R80: library part R0201-1M0, "Resistor, Â±1%, 0.05W", Manufacturer=N.A., Part number IPS=00000001418, Part number NEMS=100100093, Part number Norautron=26107108
R4: library part R0402-0R, "Resistor, Â±5%, 0.063W", Manufacturer=N.A., Part number IPS=00000007128, Part number NEMS=100100109, Supplier Part Number 1=146-9661
R9 R23 R59: library part R0201-N.C., "Not mounted", Manufacturer=N.A., Part number NEMS=100100107
R10 R34 R35 R52 R54 R56 R60 R63 R64 R65 R76 R81 R85 R86: library part R0201-100k, "Resistor, Â±1%, 0.05W", Manufacturer=N.A., Part number IPS=00000001419, Part number NEMS=100100080, Part number Norautron=26108487
R11 R12 R15 R16 R19 R20 R22 R25 R26 R27 R28 R29 R30: library part R0201-150, "Resistor, Â±1%, 0.05W", Manufacturer=N.A., Part number IPS=00000001420, Part number NEMS=100100029
R21: library part R0201-2R2, "Resistor, Â±1%, 0.05W", Manufacturer=N.A., Part number NEMS=100100006, Part number Norautron=26470029
R33 R39 R40 R41 R42: library part R0201-120, "Resistor, Â±1%, 0.05W", Manufacturer=N.A., Part number IPS=00000000880, Part number NEMS=100100028, Part number Norautron=26107076
R36 R74: library part R0201-47k, "Resistor, Â±1%, 0.05W", Manufacturer=N.A., Part number IPS=00000001423, Part number NEMS=100100076
R37 R78: library part R0201-150k, "Resistor, Â±1%, 0.05W", Manufacturer=N.A., Part number IPS=00000001422, Part number NEMS=100100082
R48 R49 R83 R84: library part R0201-4k7, "Resistor, Â±1%, 0.05W", Manufacturer=N.A., Part number IPS=00000001706, Part number NEMS=100100061
R50 R51: library part R0201-12k, "Resistor, Â±1%, 0.05W", Manufacturer=N.A., Part number IPS=00000007891, Part number NEMS=100100066, Part number Norautron=26192279
R53 R55 R57 R61: library part R0201-18k, "Resistor, Â±1%, 0.05W", Manufacturer=N.A., Part number IPS=00000001707, Part number NEMS=100100069
R58 R87: library part R0201-0R, "Resistor, Â±5%, 0.05W", Manufacturer=N.A., Part number IPS=00000003245, Part number NEMS=100100001
R68: library part R0201-1k87, "Resistor, Â±1%, 0.05W", Manufacturer=N.A., Part number NEMS=100100050
R70 R71: library part R0201-5k1, "Resistor, Â±1%, 0.05W", Manufacturer=N.A., Part number NEMS=100100565, Part number Norautron=26192285
R82: library part R0402-N.C., "Not mounted", Manufacturer=N.A., Part number NEMS=100100281
SB1 SB11 SB12 SB13 SB15 SB16 SB19 SB20 SB22 SB26 SB27 SB29 SB34: Manufacturer=N.A., Part number NEMS=100500458
SB2 SB3 SB4 SB5 SB6 SB7 SB8 SB9 SB10 SB14 SB17 SB18 SB21 SB23 SB24 SB25 SB28 SB32: library part "Solderbridge Shorted", "Shorted Solderbridge", Manufacturer=N.A., Part number NEMS=100500459
SB30 SB31 SB33 SB35: library part "Solderbridge Shorted Power", "Shorted Solderbridge Power", Manufacturer=N.A., Part number NEMS=100500460
SW1 SW2 SW3 SW4 SW5: library part L-KLS7-TS6616B-2.5-160-T, "Tactile Switch, SPNO, SMD, 160gf, 6.2x6.4x2.5mm", Manufacturer=KLS, Part number IPS=N.A., Part number NEMS="101500133, 101500001"
SW6: library part Switch-Slide-RA-J-Lead-DPDT-8.5x3.5mm_C&K, "SMD slide Switch (ON-ON)", Manufacturer=C&K, Manufacturer Part Number=JS202011JAQN, Part number IPS=00000007811, Part number NEMS=101500037, Part number Norautron=N.A., Supplier Part Number 1=CKN10722CT-ND
TP1 TP2: library part TP_SMD_Ã˜1.0MM, "1.0mm circular SMD testpad", Manufacturer="Nordic Semiconductor", Manufacturer Part Number=N.A., Part number NEMS=100500475
TP3 TP4 TP5 TP6 TP7 TP8 TP9 TP10 TP11 TP12 TP13 TP14 TP15 TP16 TP17 TP18 TP19 TP20 TP21 TP22 TP23 TP25 TP26 TP27: library part TP_SMD_Ã˜1.5MM, "1.5mm circular SMD testpad", Manufacturer="Nordic Semiconductor", Manufacturer Part Number=N.A., Part number NEMS=100500477
TP24: library part "Testpoint TH", "Testpoint, through hole", Manufacturer=N.A., Part number NEMS=100500464
U2: "GNSS Low-Noise Amplifier Front-End Module with Integrated Pre-Filter and Post-Filter", Manufacturer=Skyworks, Part number IPS=00000002997, Part number NEMS=101900584, Part number Norautron=N.A., Supplier Part Number 1=863-2032-1-ND
U3: library part nRF5340-QKAAD0, "Multi-protocol Bluetooth Low Energy, IEEE 802.15.4, ANT and 2.4GHz proprietary system-on-chip", Manufacturer="Nordic Semiconductor", Part number IPS=N.A., Part number NEMS=102000216, Part number Norautron=NOD26470035
U4: library part GD25WB256EYIG, "Quad Serial Flash, 256Mbit, 104MHz, 1.65V - 3.6V", Manufacturer=GigaDevice, Part number IPS=N.A., Part number NEMS=101900774
U5: library part PCAL6408AHK, "8-bit I2C-bus I/O expander with interrupt output", Manufacturer="NXP Semiconductors", Part number IPS=00000009987, Part number NEMS=101900289, Part number Norautron=N.A., Supplier Part Number 1=568-9944-1-ND
U6: library part M2M_UICC, "M2M UICC SIM Card", Manufacturer=N.A., Part number NEMS=101900595
U7_S1 U7_S2 U7_S3 U7_S4 U7_S5 U7_S6 U7_S8 U7_S10 U7_S11: "Data / Audio Low-Voltage Dual DPDT Analog Switch", Manufacturer="ON Semiconductor", Part number IPS=00000009986, Part number NEMS=101900422, Part number Norautron=26500608, Supplier Part Number 1=FSA2466UMXCT-ND
U8_S7 U8_S9: library part NX3DV2567GU, "Low-ohmic four-pole double-throw analog switch", Manufacturer="NXP Semiconductors", Part number IPS=00000007816, Part number NEMS=101900290, Part number Norautron=N.A., Supplier Part Number 1=568-5206-1-ND
U9: "Li-Ion/Li-Polymer USB-C battery charger with high efficiency buck regulators, LDOs or load switches, LED drivers, TWI and VBUSOUT", Manufacturer="Nordic Semiconductor", Part number IPS=N.A., Part number NEMS=102000291
X1: library part XTAL_SMD2016_32MHz_8pF_Kyocera, "XTAL SMD 2016, 32MHz, Cl=8pF, Tot: Â±40ppm", Manufacturer=Kyocera, Manufacturer Part Number=CX2016DB32000D0WZRC1, Part number IPS=00000007827, Part number NEMS=101600039, Part number Norautron=26511136, Supplier Part Number 1=1253-1586-1-ND
Y1 Y2: library part "SHUNT JUMPER 2.54mm BLACK GOLD Horizontal (obsolete)", "Shunt Jumper 2.54mm Black", Manufacturer=3M, Manufacturer Part Number=969102-0000-DA, Part Number="SHUNT JUMPER 2.54mm BLACK GOLD Horizontal (Obsolete)", Part number IPS=00000001916, Part number NEMS=100500644, Part number Norautron=N.A., Supplier Part Number 1=3M9580-ND

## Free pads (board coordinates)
  round 3.2 hole 3.2 unplated: 1(13.97,7.621) 1(15.24,55.881) 1(66.04,12.701) 1(66.04,40.641) 1(90.17,55.881) 1(96.52,7.621)

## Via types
v1: diameter 0.5, hole 0.25, Top Layer to Bottom Layer, tented both sides, 1623 vias
v2: diameter 0.3, hole 0.1, Top Layer to Mid-Layer 1, tented top, 445 vias
v3: diameter 0.3, hole 0.1, Top Layer to Mid-Layer 1, tented both sides, 97 vias
v4: diameter 0.61, hole 0.305, Top Layer to Bottom Layer, tented both sides, 9 vias

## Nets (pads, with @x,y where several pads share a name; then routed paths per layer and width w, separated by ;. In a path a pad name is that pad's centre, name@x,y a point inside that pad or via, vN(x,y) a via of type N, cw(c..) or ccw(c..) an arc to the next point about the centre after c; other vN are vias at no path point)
5V: P1.5 P5.2 P7.5 P11.2 P13.10 SB35.2 | length 89.4
  Top Layer w1: v1@7.2,10.905 8.1,10.905 8.105,10.9 v1(8.8,10.9)
  Mid-Layer 2 w1: v1(7.4,10.9) v1(8.1,10.9) v1(8.8,10.9) 8.8,8.2 10.2,6.8 11.748,5.252 36.748,5.252 37.235,4.765 38.1,4.765 ; P13.10@38.1,3.811 38.1,4.765 ; v1(68.472,35.561) v1(67.722,35.561) v1(66.972,35.561) 65.841,35.561 64.65,34.369 52.469,34.369 38.1,20 38.1,4.765
ANT: C21.2 J1.3 L1.1 | length 19.6
  Top Layer w0.1: J1.3@135.714,18.7 135.72,18.706 136.481,18.706 ccw(c136.481,20.3) 138.074,20.3 138.074,35.207 cw(c138.984,35.207) 138.984,36.117
AREF: P4.8 P10.8 P16.16 U7_S10.8 | length 74.8
  Top Layer w0.15: P16.16@23.876,59.691 P4.8@23.876,57.346 v1(23.876,55.881) P4.8@23.876,54.416 23.876,53.849 27.356,50.369 39.539,50.369 39.541,50.368 40.825,50.368 40.826,50.369 48.131,50.369 50,48.5 50,39.887 ccw(c51.8,39.887) 50.525,38.617 51.742,37.4 ccw(c53.012,38.675) 53.012,36.875 59.742,36.875 60.294,36.322 60.294,33.717 60.569,33.442 v1(60.569,28.808) ; U7_S10.8@59.1,22.025 v1(60,22.025) v1@60.086,22.025
  Bottom Layer w0.15: P10.8@23.876,53.849 v1(23.876,55.881) P10.8@23.876,57.346 ; v1(60,22.025) 59.989,22.025 58.975,23.039 58.975,27.213 v1(60.569,28.808)
BTN1_EXT: D1.1 R52.1 R53.2 U7_S6.15 | length 7.3
  Top Layer w0.15: U7_S6.15@103.61,26.259 v2(103.61,26.825) ; R53.2@106.399,29.581 106.723,29.581 v2(107.048,29.906) 106.723,30.231 D1.1@106.399,30.231
  Mid-Layer 1 w0.15: v2(103.61,26.825) 104.26,27.475 104.26,28.236 104.548,28.525 105.71,28.525 107.048,29.863 v2(107.048,29.906)
BTN2_EXT: D2.1 R54.1 R55.2 U7_S6.3 | length 8
  Top Layer w0.15: v2(103.714,27.539) 103.859,27.684 U7_S6.3@104.235,27.684 ; R55.2@106.399,31.055 106.723,31.055 v2(107.048,31.379) 106.723,31.704 D2.1@106.399,31.704
  Mid-Layer 1 w0.15: v2(103.714,27.539) 103.985,27.81 103.985,28.35 104.435,28.8 105.596,28.8 106.698,29.902 106.698,31.029 v2(107.048,31.379)
BTN3_EXT: D3.1 R56.1 R57.2 U7_S6.7 | length 8.6
  Top Layer w0.15: U7_S6.7@103.21,28.709 103.21,28.962 103.481,29.234 104.646,29.234 104.652,29.228 105.032,29.228 v2(105.11,29.15) ; R57.2@106.399,32.528 106.723,32.528 v2(107.048,32.852) 106.723,33.177 D3.1@106.399,33.177
  Mid-Layer 1 w0.15: v2(105.11,29.15) 105.557,29.15 106.423,30.016 106.423,32.227 v2(107.048,32.852)
BTN4_EXT: D4.1 R60.1 R61.2 U7_S6.11 | length 12.1
  Top Layer w0.15: U7_S6.11@102.585,27.284 102.951,27.284 103.21,27.025 v2(103.21,26.975) ; R61.2@106.399,34.001 106.723,34.001 v2(107.048,34.326) 106.723,34.65 D4.1@106.399,34.65
  Mid-Layer 1 w0.15: v2(103.21,26.975) 103.085,27.1 103.085,28.229 103.348,28.493 103.721,28.493 103.73,28.484 104.802,29.556 105.574,29.556 106.148,30.13 106.148,33.426 v2(107.048,34.326)
BUTTON1: SW1.2 U7_S6.16 | length 42.6
  Top Layer w0.152: U7_S6.16@104.01,26.259 v1(104.547,26.259)
  Mid-Layer 1 w0.125: v2(114.6,15) 114.647,15 114.747,14.9 v1(121.5,14.9)
  Bottom Layer w0.15: v1(104.547,26.259) 104.547,23.576 105.694,22.428 111.028,22.428 111.525,22.925 111.525,25.256 114.708,28.438 116.889,28.438 118.013,27.315 118.013,22.913 117.662,22.563 117.662,18.738 v1(121.5,14.9)
BUTTON2: SW2.2 U7_S6.4 | length 45.6
  Top Layer w0.125: v1(128.75,15) SW2.2@130.665,15
  Top Layer w0.152: U7_S6.4@104.235,28.084 v1@104.904,28.084
  Bottom Layer w0.15: v1(104.904,28.009) 105.267,27.647 105.267,23.734 105.562,23.438 ccw(c105.687,23.439) 105.599,23.351 105.905,23.045 106.211,22.739 ccw(c106.299,22.828) 106.298,22.703 110.903,22.703 111.25,23.05 111.25,25.37 114.594,28.713 117.003,28.713 118.288,27.429 118.288,22.8 117.937,22.45 117.937,19.564 122.401,15.1 v1(125.7,15.1) 125.75,15.05 128.7,15.05 v1(128.75,15)
BUTTON3: SW3.2 U7_S6.8 | length 63.1
  Top Layer w0.125: SW3.2@114.815,2 SW3.2@120.665,2 121.45,2 122.338,2.888 124.188,2.888 v1(124.5,3.2)
  Top Layer w0.152: v1(102.273,28.709) U7_S6.8@102.81,28.709
  Bottom Layer w0.15: v1(102.273,28.709) 101.4,27.836 101.4,25.552 102.077,24.875 102.47,24.875 105.467,21.878 111.278,21.878 112.1,22.7 112.1,25.05 114.938,27.888 116.661,27.888 117.463,27.087 117.463,23.141 117.112,22.791 117.112,18.099 124.5,10.711 v1(124.5,3.2)
BUTTON4: SW4.2 U7_S6.12 | length 58.1
  Top Layer w0.125: SW4.2@125.115,2 125.2,2.085 v1(125.2,3.2) ; SW4.2@125.265,2 SW4.2@131.165,2
  Top Layer w0.152: v1(101.915,26.884) U7_S6.12@102.585,26.884
  Bottom Layer w0.15: v1(101.915,26.884) 101.915,25.426 102.191,25.15 102.583,25.15 105.58,22.153 111.153,22.153 111.8,22.8 111.8,25.142 114.822,28.163 116.775,28.163 117.738,27.201 117.738,23.027 117.387,22.677 117.387,18.213 125.2,10.4 v1(125.2,3.2)
COEX0: M1.52 P24.1 P27.1 R6.1 R7.2 U7_S11.1 | length 114.5
  Top Layer w0.15: U7_S11.1@57.018,45.475 57.018,45.668 57.3,45.95 v2(58,45.95) ; v2(59.1,45.95) 60.043,45.95 62.343,48.25 63.08,48.25 66.9,52.07 v1(66.9,52.35) ; v1(90.4,49.75) 90.4,51.975 P24.1@91.766,53.341 ; M1.52@129.225,26.25 129.3,26.175 129.53,26.175 129.609,26.097 129.982,26.097 130.032,26.147 130.257,26.147 v1(130.324,26.214) ; R6.1@137.675,38.887 137.681,38.894 137.994,38.894 v1(138,38.9) ; v1@137.987,38.887 R7.2@138.25,38.887
  Mid-Layer 1 w0.15: v2(58,45.95) v2(59.1,45.95)
  Mid-Layer 2 w0.15: v1(130.324,26.214) ccw(c130.335,26.804) 130.925,26.804 130.925,30.925 cw(c131.466,30.925) 131.466,31.466 132.189,31.466 ccw(c132.191,31.925) 132.65,31.926 132.65,34.801 cw(c134.153,34.802) 133.084,35.859 135.803,38.578 ; 135.804,38.579 cw(c136.575,37.813) 136.576,38.9 v1(138,38.9)
  Bottom Layer w0.15: v1(66.9,52.35) 67.559,51.691 87.495,51.691 89.436,49.75 v1(90.4,49.75) 91.054,49.096 103.808,49.096 108.829,44.075 110.814,44.075 122.106,32.783 127.32,32.783 130.45,29.653 130.45,28.487 cw(c130.3,28.487) 130.406,28.381 129.919,27.894 cw(c129.813,28) 129.813,27.85 129.712,27.85 ccw(c129.712,27.7) 129.606,27.806 129.348,27.548 ccw(c129.455,27.443) 129.305,27.443 129.305,26.401 129.609,26.097 130.112,26.097 130.23,26.214 v1(130.324,26.214)
  other v1: 93.028,53.341
COEX1: M1.53 P24.2 P27.2 U7_S11.5 | length 99.2
  Top Layer w0.15: U7_S11.5@55.193,45.25 55.193,46.143 v2(55.5,46.45) ; v2(59.1,46.45) 60.154,46.45 66.754,53.05 v1(66.836,53.05) ; v1(94.5,49.75) 94.567,49.817 94.866,49.817 95.254,50.205 95.254,52.393 96.203,53.341 v1(97.473,53.341) ; M1.53@129.225,26.75 129.3,26.75 129.375,26.675 129.572,26.675 129.7,26.547 v1(129.795,26.547)
  Mid-Layer 1 w0.15: v2(55.5,46.45) v2(59.1,46.45)
  Bottom Layer w0.15: v1(66.836,53.05) 67.92,51.966 87.798,51.966 89.564,50.2 90.586,50.2 91.036,49.75 v1(94.5,49.75) 94.513,49.75 94.513,49.737 94.879,49.371 103.922,49.371 108.943,44.35 110.928,44.35 122.22,33.058 127.434,33.058 130.725,29.767 130.725,28.3 130,27.575 129.842,27.575 129.58,27.312 129.58,26.857 129.795,26.641 v1(129.795,26.547)
COEX2: M1.54 P24.3 P27.3 R3.2 U7_S11.9 | length 99.4
  Top Layer w0.15: v2(55.805,42.825) 55.812,42.832 55.812,43.819 U7_S11.9@55.818,43.825 ; v2(56.6,42.363) 56.613,42.35 59.793,42.35 61.1,43.657 61.1,46.618 62.457,47.975 63.194,47.975 67.35,52.131 67.35,53.173 v1(66.773,53.75) ; M1.54@129.225,27.25 129.811,27.25 129.935,27.126 v1(130.03,27.126) 130.043,27.113 130.902,27.113 R3.2@130.915,27.1
  Mid-Layer 1 w0.15: v2(55.805,42.825) 56.239,42.391 56.571,42.391 v2(56.6,42.363)
  Bottom Layer w0.15: v1(66.773,53.75) 68.281,52.242 87.911,52.242 89.352,50.801 v1(93.028,50.801) 94.298,50.801 95.452,49.646 104.063,49.646 109.084,44.625 111.119,44.625 122.411,33.333 127.547,33.333 131,29.881 131,28.096 130.419,27.515 v1(130.03,27.126)
COEX_SELECT: R66.2 TP11.1 U3.AK14 U7_S11.2 U7_S11.10 | length 63.5
  Top Layer w0.125: v1(22.2,22.55) TP11.1@23,21.75 ; v1(31.436,20.55) 32.134,20.55 32.571,20.988 38.78,20.988 39.28,20.488 47.216,20.488 53.6,26.871 53.6,35.86 53.162,36.298 v2(53.162,36.35) ; v2(53.162,40.575) 52.63,40.575 52.4,40.805 52.4,41.225 52.5,41.325 54.85,41.325 56.145,42.62 56.145,42.777 56.218,42.85 U7_S11.10@56.218,43.825 56.218,44.068 56.618,44.468 U7_S11.2@56.618,45.475
  Mid-Layer 1 w0.125: v1(22.2,22.55) 22.937,23.288 23.769,23.288 24.325,23.843 24.325,25.347 v2@24.525,25.547 ; v2@24.49,25.582 24.525,25.617 v2(24.525,25.659) ; v2(53.162,36.35) v2(53.162,40.575)
  Bottom Layer w0.125: v1(22.2,22.55) 26.819,22.55 28.269,21.1 30.7,21.1 31.25,20.55 v1(31.436,20.55)
COM.CH1_S1: R11.2 TP3.1 U7_S1.16 | length 73
  Top Layer w0.125: R11.2@30.06,27.55 33.175,27.55 33.475,27.85 v1(33.475,27.875) ; v1(34.125,18.6) 33.875,18.85 33.22,18.85 TP3.1@33.02,19.05 33.958,19.988 38.366,19.988 40.491,17.863 44.887,17.863 44.973,17.948 46.09,17.948 54.6,26.457 54.6,36.035 54.863,36.298 v2(54.863,36.35) ; v2(54.863,40.55) 54.863,40.565 56.073,41.775 59.943,41.775 61.612,43.445 61.612,46.406 62.669,47.463 65.688,47.463 v2(66.025,47.125) ; U7_S1.16@66.025,45.25 v2(66.025,45.7)
  Mid-Layer 1 w0.125: v2(54.863,36.35) v2(54.863,40.55) v2@54.863,40.575 ; v2(66.025,45.7) v2(66.025,47.125)
  Bottom Layer w0.125: v1(33.475,27.875) 33.25,27.65 33.25,26.117 33.663,25.704 33.663,19.063 v1(34.125,18.6)
COM.CH1_S9: P28.2 P30.1 SB12.2 U8_S9.16 | length 26.5
  Top Layer w0.254: U8_S9.16@87.5,19.275 87.498,19.277 87.498,19.615 87.148,19.965 87.148,21.093 87.342,21.287 89.266,21.287 93.778,16.775 95.46,16.775 P28.2@95.46,15.7 95.46,14.865 96.088,14.237 101.942,14.237 103.353,12.825 104.73,12.825 P30.1@104.73,11.8 ; P30.1@105.237,12.928 105.237,13.549 105.688,14
COM.CH1_S11: P3.3 P9.3 U7_S11.16 | length 16.1
  Top Layer w0.15: U7_S11.16@57.643,45.25 58,45.25 58.42,45.67 P3.3@58.42,54.416 P3.3@58.42,57.346
  Bottom Layer w0.15: P9.3@58.42,53.824 P9.3@58.42,54.416 v1(58.42,55.881) P9.3@58.42,57.346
